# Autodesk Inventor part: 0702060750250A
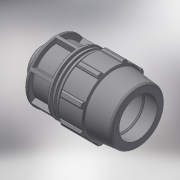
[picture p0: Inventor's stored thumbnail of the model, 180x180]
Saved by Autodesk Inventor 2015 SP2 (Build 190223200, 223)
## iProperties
Created: 2017-02
Part Number: 0702060750250A
Material: Generic
Description: PLASSON MALE ADAPTOR 75-2.1/2"
Document SubType Name: Modeling
Designer: KIM
Mass: 964.158 g
Surface Area: 1468.9 cm^2
Volume: 964.158 cm^3
Density: 1 g/cm^3
Appearance: Default
Author: KIM
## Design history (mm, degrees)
derived "87020.ipt"
feature "Solid1::87020.ipt"
tag "TaggingFeature1"
body "Solid1"
other parameters: "d2" = 75, "d4" = 27.28571, "d5" = 47.75, "d7" = 132, "d8" = 99, "d9" = 27.28571, "d11" = 5.45714, "d12" = 105.6, "d13" = 120 deg, "d14" = 97.5, "d15" = 6 deg, "d16" = 118.8, "d18" = 3.75, "d19" = 35 deg, "d20" = 17.5 deg, "d21" = 122.76, "d23" = 0, "d25" = 360 deg, "d27" = 2.64, "d34" = 6.6, "d36" = 0, "d42" = 47.75, "d43" = 3.96, "d46" = 2.25, "d51" = 191, "d52" = 29, "d53" = 1.5, "d55" = 360 deg, "d57" = 75.184, "d58" = 52.6288, "d59" = 38.2, "d61" = 116.424, "d62" = 3.47714, "d63" = 3.47714, "d66" = 6.95429, "d_" = 75, "E_" = 132, "H_" = 191, "l_2" = 29, "R_" = 75.184, "d60" = 17.38571
